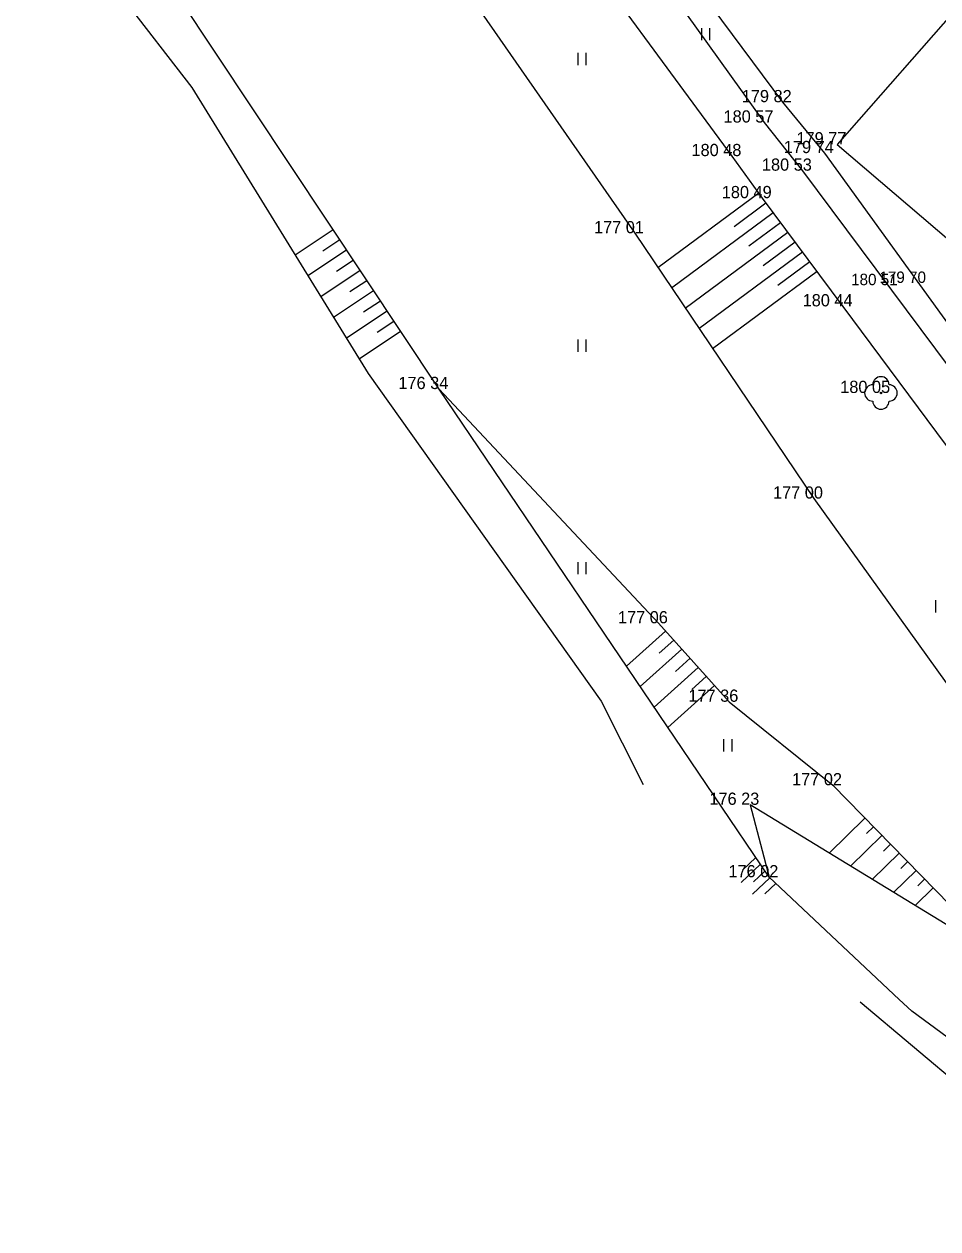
# Model space of a CAD drawing. Extents: x -537755 to -537431, y -1180722 to -1180510.
# Drawn here: x -537643.4 to -537587.3, y -1180697.4 to -1180623.4 of the extents above; entities that cross this region are included whole.
import ezdxf

# ---------------------------------------------------------------- set-up
doc = ezdxf.new("R2010")
doc.units = 0
for name, color, linetype in [('Vrstva 1', 7, 'Continuous'), ('Vrstva 11', 7, 'Continuous'), ('Vrstva 14', 7, 'Continuous'), ('Vrstva 15', 7, 'Continuous'), ('Vrstva 22', 7, 'Continuous'), ('Vrstva 3', 7, 'Continuous'), ('Vrstva 36', 7, 'Continuous')]:
    doc.layers.add(name, color=color, linetype=linetype)

msp = doc.modelspace()

# ---------------------------------------------------------------- linework, layer by layer
at = {"layer": 'Vrstva 1'}
for p, q in [((-537596.83, -1180628.15), (-537596.83, -1180628.15)), ((-537597.95, -1180629.4), (-537597.95, -1180629.4)), ((-537593.47, -1180630.74), (-537593.47, -1180630.74)), ((-537599.92, -1180631.46), (-537599.92, -1180631.46)), ((-537594.246, -1180631.276), (-537594.246, -1180631.276)), ((-537595.592, -1180632.357), (-537595.592, -1180632.357)), ((-537598.059, -1180634.045), (-537598.059, -1180634.045)), ((-537605.91, -1180636.2), (-537605.91, -1180636.2)), ((-537588.54, -1180639.25), (-537588.54, -1180639.25)), ((-537590.28, -1180639.39), (-537590.28, -1180639.39)), ((-537593.09, -1180640.69), (-537593.09, -1180640.69)), ((-537617.93, -1180645.77), (-537617.93, -1180645.77)), ((-537590.78, -1180646.01), (-537590.78, -1180646.01)), ((-537594.91, -1180652.5), (-537594.91, -1180652.5)), ((-537604.44, -1180660.16), (-537604.44, -1180660.16)), ((-537600.11, -1180664.98), (-537600.11, -1180664.98)), ((-537593.74, -1180670.11), (-537593.74, -1180670.11)), ((-537598.82, -1180671.31), (-537598.82, -1180671.31)), ((-537597.65, -1180675.76), (-537597.65, -1180675.76)), ((-537588.89, -1180683.98), (-537588.89, -1180683.98))]:
    msp.add_line(p, q, dxfattribs=at)
at = {"layer": 'Vrstva 11'}
for p, q in [((-537583.093, -1180618.912), (-537593.47, -1180630.74)), ((-537593.47, -1180630.74), (-537569.85, -1180650.97))]:
    msp.add_line(p, q, dxfattribs=at)
at = {"layer": 'Vrstva 14'}
for p, q in [((-537643.43, -1180613.91), (-537633.13, -1180627.24)), ((-537608.311, -1180614.935), (-537597.95, -1180629.4)), ((-537617.93, -1180645.77), (-537636.81, -1180617.37)), ((-537617.24, -1180619.892), (-537605.91, -1180636.2)), ((-537633.13, -1180627.24), (-537622.28, -1180644.81)), ((-537596.83, -1180628.15), (-537594.246, -1180631.276)), ((-537597.95, -1180629.4), (-537595.592, -1180632.357)), ((-537594.246, -1180631.276), (-537583.28, -1180646.46)), ((-537595.592, -1180632.357), (-537584.444, -1180647.34)), ((-537605.91, -1180636.2), (-537594.91, -1180652.5)), ((-537573.42, -1180667.21), (-537593.09, -1180640.69)), ((-537622.28, -1180644.81), (-537607.98, -1180664.94)), ((-537617.93, -1180645.77), (-537604.44, -1180660.16)), ((-537597.65, -1180675.76), (-537617.93, -1180645.77)), ((-537594.91, -1180652.5), (-537584.28, -1180667.29)), ((-537604.44, -1180660.16), (-537600.11, -1180664.98)), ((-537607.98, -1180664.94), (-537605.38, -1180670.07)), ((-537600.11, -1180664.98), (-537593.74, -1180670.11)), ((-537593.74, -1180670.11), (-537584.511, -1180679.533)), ((-537584.89, -1180679.808), (-537598.82, -1180671.31)), ((-537598.82, -1180671.31), (-537597.65, -1180675.76)), ((-537589.649, -1180683.268), (-537597.65, -1180675.76)), ((-537592.06, -1180683.41), (-537575.48, -1180697.36)), ((-537588.89, -1180683.98), (-537589.649, -1180683.268)), ((-537575.7, -1180693.73), (-537588.89, -1180683.98))]:
    msp.add_line(p, q, dxfattribs=at)
for points in [[(-537599.92, -1180631.46), (-537611.174, -1180616.178)], [(-537605.52, -1180616.45), (-537596.83, -1180628.15)], [(-537598.059, -1180634.045), (-537599.92, -1180631.46)], [(-537593.09, -1180640.69), (-537598.059, -1180634.045)]]:
    msp.add_lwpolyline(points, dxfattribs=at)
at = {"layer": 'Vrstva 15'}
for p, q in [((-537604.485, -1180638.311), (-537598.289, -1180633.726)), ((-537599.798, -1180635.776), (-537597.845, -1180634.331)), ((-537603.645, -1180639.556), (-537597.396, -1180634.932)), ((-537598.906, -1180636.982), (-537596.947, -1180635.532)), ((-537626.781, -1180637.522), (-537624.444, -1180635.969)), ((-537602.805, -1180640.801), (-537596.497, -1180636.133)), ((-537625.064, -1180637.281), (-537624.029, -1180636.593)), ((-537598.013, -1180638.187), (-537596.049, -1180636.733)), ((-537625.992, -1180638.799), (-537623.614, -1180637.218)), ((-537601.966, -1180642.045), (-537595.6, -1180637.334)), ((-537625.204, -1180640.075), (-537622.784, -1180638.467)), ((-537624.234, -1180638.53), (-537623.199, -1180637.843)), ((-537597.121, -1180639.393), (-537595.15, -1180637.935)), ((-537623.404, -1180639.779), (-537622.369, -1180639.092)), ((-537601.126, -1180643.289), (-537594.701, -1180638.535)), ((-537624.415, -1180641.352), (-537621.953, -1180639.716)), ((-537622.573, -1180641.029), (-537621.538, -1180640.341)), ((-537623.626, -1180642.63), (-537621.123, -1180640.966)), ((-537621.743, -1180642.278), (-537620.708, -1180641.59)), ((-537622.838, -1180643.906), (-537620.293, -1180642.215)), ((-537606.418, -1180662.794), (-537604.014, -1180660.634)), ((-537604.408, -1180661.996), (-537603.513, -1180661.192)), ((-537605.57, -1180664.048), (-537603.012, -1180661.75)), ((-537604.721, -1180665.303), (-537602.009, -1180662.866)), ((-537603.405, -1180663.112), (-537602.51, -1180662.308)), ((-537602.402, -1180664.228), (-537601.508, -1180663.424)), ((-537603.874, -1180666.557), (-537601.007, -1180663.981)), ((-537593.959, -1180674.275), (-537591.765, -1180672.126)), ((-537592.639, -1180675.081), (-537590.716, -1180673.198)), ((-537591.664, -1180673.077), (-537591.24, -1180672.662)), ((-537590.614, -1180674.148), (-537590.191, -1180673.734)), ((-537598.473, -1180674.544), (-537599.293, -1180675.321)), ((-537591.317, -1180675.887), (-537589.666, -1180674.27)), ((-537598.189, -1180674.963), (-537599.373, -1180676.086)), ((-537597.905, -1180675.383), (-537598.605, -1180676.047)), ((-537589.997, -1180676.692), (-537588.617, -1180675.341)), ((-537589.564, -1180675.221), (-537589.141, -1180674.806)), ((-537597.612, -1180675.795), (-537598.666, -1180676.794)), ((-537597.247, -1180676.138), (-537597.917, -1180676.773)), ((-537588.515, -1180676.292), (-537588.092, -1180675.877)), ((-537588.675, -1180677.499), (-537587.567, -1180676.413))]:
    msp.add_line(p, q, dxfattribs=at)
at = {"layer": 'Vrstva 22'}
msp.add_circle((-537590.78, -1180646.01), 0.05, dxfattribs=at)
for centre, start, end in [((-537590.78, -1180645.51), 0, 180), ((-537591.28, -1180646.01), 90, 270), ((-537590.28, -1180646.01), 270, 90), ((-537590.78, -1180646.51), 180, 0)]:
    msp.add_arc(centre, 0.5, start, end, dxfattribs=at)
at = {"layer": 'Vrstva 36'}
for p, q in [((-537601.791, -1180624.344), (-537601.791, -1180623.594)), ((-537601.291, -1180624.344), (-537601.291, -1180623.594)), ((-537609.393, -1180625.867), (-537609.393, -1180625.117)), ((-537608.893, -1180625.867), (-537608.893, -1180625.117)), ((-537609.393, -1180643.486), (-537609.393, -1180642.736)), ((-537608.893, -1180643.486), (-537608.893, -1180642.736)), ((-537609.393, -1180657.147), (-537609.393, -1180656.397)), ((-537608.893, -1180657.147), (-537608.893, -1180656.397)), ((-537587.414, -1180659.495), (-537587.414, -1180658.745)), ((-537600.43, -1180668.033), (-537600.43, -1180667.283)), ((-537599.93, -1180668.033), (-537599.93, -1180667.283))]:
    msp.add_line(p, q, dxfattribs=at)

# ---------------------------------------------------------------- texts
at = {"layer": 'Vrstva 3'}
for s, height, p in [('179 82 ', 0.75, (-537599.33, -1180628.15)), ('180 57 ', 0.75, (-537600.45, -1180629.4)), ('179 77 ', 0.75, (-537595.97, -1180630.74)), ('180 48 ', 0.75, (-537602.42, -1180631.46)), ('179 74 ', 0.75, (-537596.746, -1180631.276)), ('180 53 ', 0.75, (-537598.092, -1180632.357)), ('180 49 ', 0.75, (-537600.559, -1180634.045)), ('177 01 ', 0.75, (-537608.41, -1180636.2)), ('180 51 ', 0.7, (-537592.613, -1180639.39)), ('179 70 ', 0.7, (-537590.873, -1180639.25)), ('180 44 ', 0.75, (-537595.59, -1180640.69)), ('176 34 ', 0.75, (-537620.43, -1180645.77)), ('180 05 ', 0.75, (-537593.28, -1180646.01)), ('177 00 ', 0.75, (-537597.41, -1180652.5)), ('177 06 ', 0.75, (-537606.94, -1180660.16)), ('177 36 ', 0.75, (-537602.61, -1180664.98)), ('177 02 ', 0.75, (-537596.24, -1180670.11)), ('176 23 ', 0.75, (-537601.32, -1180671.31)), ('176 02 ', 0.75, (-537600.15, -1180675.76))]:
    msp.add_text(s, height=height, dxfattribs=at).set_placement(p)

doc.saveas('drawing.dxf')
